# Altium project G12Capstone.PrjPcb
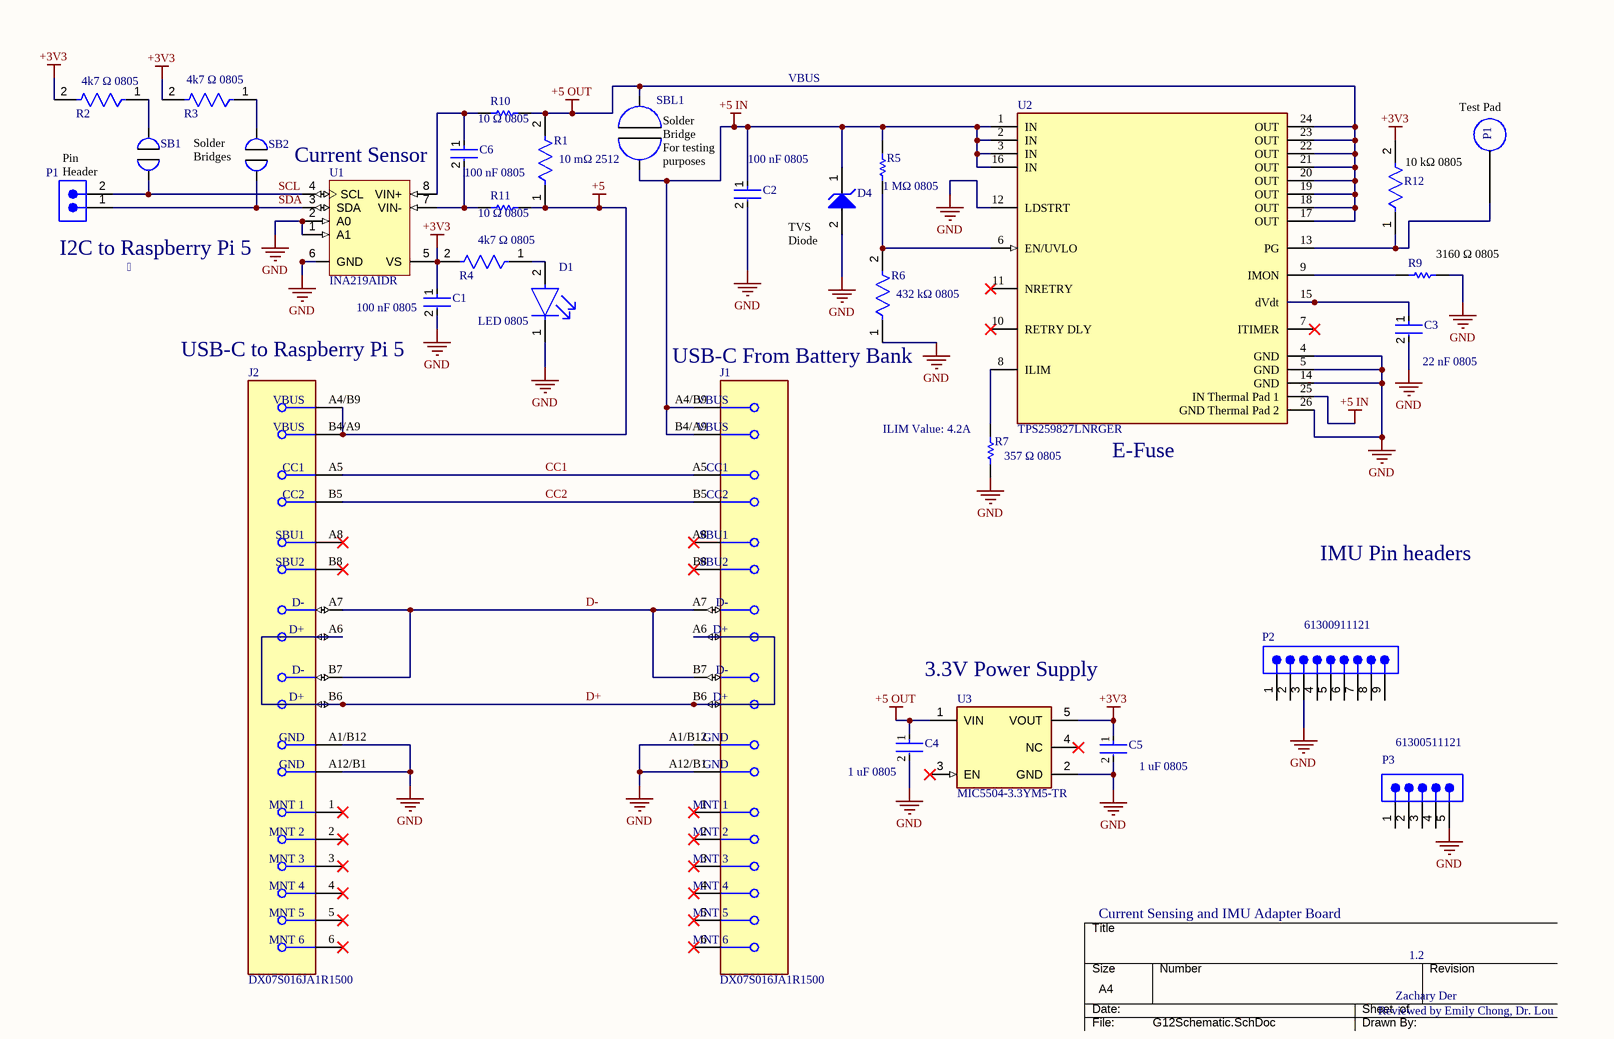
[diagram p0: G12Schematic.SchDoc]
1 sheet, 31 parts. Net scope: global (net labels, ports and power ports of the same name join across sheets).
Board file: G12PCB1.PcbDoc

## Sheet G12Schematic.SchDoc
size A4; SheetNumber: 1; SheetTotal: 1

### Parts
C1  C0805C104K5RACTU  [FP-C0805C-DN-MFG]  (value not drawn)
C2  C0805C104K5RACTU  [FP-C0805C-DN-MFG]  (value not drawn)
C3  C0805C223J1RACAUTO  [FP-C0805C-DN-MFG]  (value not drawn)
C4  08051C105K4T2A  [FP-0805-L_2_01_0_2-W_1_25-MFG]  (value not drawn)
C5  08051C105K4T2A  [FP-0805-L_2_01_0_2-W_1_25-MFG]  (value not drawn)
C6  C0805C104K5RACTU  [FP-C0805C-DN-MFG]  (value not drawn)
D1  APHCM2012CGCK-F01  [FP-APHCM2012CGCK-F01-MFG]  (value not drawn)
D4  SD05T1G  [ONSC-SOD-323-2-477-02_G_V]  (value not drawn)
J1  DX07S016JA1R1500  [FP-DX07S016JA1R1500-MFG]
J2  DX07S016JA1R1500  [FP-DX07S016JA1R1500-MFG]
P1  61300211121  [61300211121]  (value not drawn)
P2  61300911121  [61300911121]
P3  61300511121  [61300511121]
R1  CSRF2512FT10L0  [FP-CSRF2512-IPC_B]  (value not drawn)
R2  CRGCQ0805F4K7  [FP-CRGCQ0805-IPC_C]  (value not drawn)
R3  CRGCQ0805F4K7  [FP-CRGCQ0805-IPC_C]  (value not drawn)
R4  CRGCQ0805F4K7  [FP-CRGCQ0805-IPC_C]  (value not drawn)
R5  RV0805FR-071ML  [RESC2013X60X35NL10T20]  (value not drawn)
R6  CR0805-FX-4323ELF  [FP-CR0805-IPC_A]  (value not drawn)
R7  RC0805FR-07357RL  [RESC2013X60X35ML10T20]  (value not drawn)
R9  RC0805FR-07316RL  [RESC2013X60X35NL10T20]  (value not drawn)
R10  ERJ-6ENF10R0V  [RESC2013X70X40NL20T20]  (value not drawn)
R11  ERJ-6ENF10R0V  [RESC2013X70X40NL20T20]  (value not drawn)
R12  CRGCQ0805J10K  [FP-CRGCQ0805-IPC_C]  (value not drawn)
SB1  Solder Bridge  [Solder Bridge]  (value not drawn)
SB2  Solder Bridge  [Solder Bridge]  (value not drawn)
SBL1  Solder Bridge (Large)  [Solder Bridge (Large)]  (value not drawn)
TP_1  TP_1  [Test Pad]  (value not drawn)  (no BOM)
U1  INA219AIDR  [D0008A_L]
U2  TPS259827LNRGER  [FP-RGE0024M-MFG]
U3  MIC5504-3.3YM5-TR  [FP-SOT23-5LD-PL-1-MFG]

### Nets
+3V3: C1.1 C5.1 R2.2 R3.2 R4.2 R12.2 U1.5(VS) U3.5(VOUT)
+5: J2.A4/B9(VBUS) J2.B4/A9(VBUS) R1.1 R11.2
+5 IN: C2.1 D4.1(K) J1.A4/B9(VBUS) J1.B4/A9(VBUS) R5.2 SBL1.1 U2.1(IN) U2.2(IN) U2.3(IN) U2.16(IN) U2.25(IN_Thermal_Pad_1)
+5 OUT: C4.1 R1.2 R10.2 SBL1.2 U2.17(OUT) U2.18(OUT) U2.19(OUT) U2.20(OUT) U2.21(OUT) U2.22(OUT) U2.23(OUT) U2.24(OUT) U3.1(VIN)
GND: C1.2 C2.2 C3.2 C4.2 C5.2 D1.1(C) D4.2(A) J1.A1/B12(GND) J1.A12/B1(GND) J2.A1/B12(GND) J2.A12/B1(GND) P2.3 P3.5 R6.1 R7.1 R9.2 U1.1(A1) U1.2(A0) U1.6(GND) U2.4(GND) U2.5(GND) U2.12(LDSTRT) U2.14(GND) U2.26(GND_Thermal_Pad_2) U3.2(GND)
CC1: J1.A5(CC1) J2.A5(CC1)
CC2: J1.B5(CC2) J2.B5(CC2)
D+: J1.A6(D+) J1.B6(D+) J2.A6(D+) J2.B6(D+)
D-: J1.A7(D-) J1.B7(D-) J2.A7(D-) J2.B7(D-)
SCL: P1.2 SB1.1 U1.4(SCL)
SDA: P1.1 SB2.1 U1.3(SDA)
NetC3_1: C3.1 U2.15(dVdt)
NetC6_1: C6.1 R10.1 U1.8(VIN+)
NetC6_2: C6.2 R11.1 U1.7(VIN-)
NetD1_2: D1.2(A) R4.1
NetR2_1: R2.1 SB1.2
NetR3_1: R3.1 SB2.2
NetR5_1: R5.1 R6.2 U2.6(EN/UVLO)
NetR7_2: R7.2 U2.8(ILIM)
NetR9_1: R9.1 U2.9(IMON)
NetR12_1: R12.1 TP_1.4 U2.13(PG)

Not connected (* = marked no-connect by the designer): J1 1(MNT_1)* 2(MNT_2)* 3(MNT_3)* 4(MNT_4)* 5(MNT_5)* 6(MNT_6)* A8(SBU1)* B8(SBU2)*; J2 1(MNT_1)* 2(MNT_2)* 3(MNT_3)* 4(MNT_4)* 5(MNT_5)* 6(MNT_6)* A8(SBU1)* B8(SBU2)*; P2 1 2 4 5 6 7 8 9; P3 1 2 3 4; U2 7(ITIMER)* 10(RETRY_DLY)* 11(NRETRY)*; U3 3(EN)* 4(NC)*

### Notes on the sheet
- (near R2) 4k7 Ω 0805
- (near R3) 4k7 Ω 0805
- VBUS
- (near TP_1) Test Pad
- (near P1) Pin Header
- Solder
  Bridges
- Current Sensor
- 100 nF 0805
- (near R10) 10 Ω 0805
- 10 mΩ 2512
- Solder
  Bridge
  For testing purposes
- (near C2) 100 nF 0805
- (near R12) 10 kΩ 0805
- (near R4) 4k7 Ω 0805
- (near R11) 10 Ω 0805
- (near D4) TVS
  Diode
- (near R5) 1 MΩ 0805
- I2C to Raspberry Pi 5
- 
- (near C1) 100 nF 0805
- (near R6) 432 kΩ 0805
- (near R9) 3160 Ω 0805
- USB-C to Raspberry Pi 5
- (near D1) LED 0805
- USB-C From Battery Bank
- (near C3) 22 nF 0805
- (near R7) ILIM Value: 4.2A
- (near R7) 357 Ω 0805
- (near U2) E-Fuse
- IMU Pin headers
- (near U3) 3.3V Power Supply
- (near C4) 1 uF 0805
- (near C5) 1 uF 0805
- Current Sensing and IMU Adapter Board
- 1.2
- Reviewed by Emily Chong, Dr. Lou
- Zachary Der

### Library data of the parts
C1 C2 C6 = CMP-2007-00279-2: CAP CER 0.1UF 50V X7R 0805; Manufacturer: KEMET; Value: 0.10 μF; Tolerance: 0.1; Temperature Coefficient: 30ppm/°C; Material: Ceramic
C3 = CMP-03020-025363-1: C0805 22,000 pF X7R 30ppm/°C 5.00% 100 V; Manufacturer: KEMET; Voltage Rating: 100 V; Material: Ceramic; Tolerance: 0.05
C4 C5 = CMP-07738-122049624-1: 08051C105K4T2A Cap Ceramic 1uF 100V X7R 10% Pad SMD 0805 125C Automotive T/R; Capacitance: 1µF
D1 = CMP-44529-000062-1: LED GREEN CLEAR CHIP SMD; Dominant Wavelength: 570nm; Forward Current: 20mA; Number of LEDs: 1; Luminous Intensity: 40mcd; Forward Voltage: 2.1V; Viewing Angle: 110°
D4 = CMP-1061-00629-1: Transient Voltage Suppressor Diode, for ESD Protection, 2-Pin SOD-323, Pb-Free, Tape and Reel; Manufacturer: On Semiconductor; PPK Max (W): 350; IR Max (uA): 10; Direction: Unidirectional
J1 J2 = CMP-19038-000003-1: CONN RCP USB2.0 TYP C 24P SMD RA
P1 = CMP-1712-00002-7: THT Vertical Pin Header WR-PHD, Pitch 2.54 mm, Single Row, 2 pins; Pitch: 2.54mm; Number of Contacts: 2; Connector Type: Male Pin; Gender: Male; Contact Resistance: 20mΩ; Operating Supply Voltage: 250V; Current Rating: 3A
P2 = CMP-1502-01080-3: NexarPartId: 32855536; Current Rating: 3A; Connector Type: Male Pin; Operating Supply Voltage: 250V; Contact Resistance: 20mΩ; Pitch: 2.54mm; Number of Contacts: 9; Gender: Male
P3 = CMP-1502-01068-4: THT Vertical Pin Header WR-PHD, Pitch 2.54 mm, Single Row, 5 pins; Number of Contacts: 5; Connector Type: Male Pin; Operating Supply Voltage: 250V; Contact Resistance: 20mΩ; Gender: Male; Pitch: 2.54mm; Current Rating: 3A
R1 = CMP-26527-001250-1: Foil on Ceramic Current Sensing Chip Resistor 10mΩ ±1% 2W 2512 AEC Qualified; Resistance: 10mR; Temperature Coefficient: 100ppm/°C
R2-R4 = CMP-03211-010668-1: CRGCQ0805 4.7KΩ 0.125W ±100ppm/°C 1% 150V; Manufacturer: TE Connectivity; Automotive Grade: Grade 837; Tolerance: 0.01
R5 = CMP-2001-01791-1: Manufacturer: Yageo
R6 = CMP-07231-005639-1: Thick Film Chip Resistors 0805 432kΩ 0.125W 1% 100ppm/°C; Voltage Rating: 150V; Resistance: 432kR; Power Rating: 125mW
R7 = CMP-2001-01096-1: Manufacturer: Yageo
R9 = CMP-2001-01081-1: Manufacturer: Yageo
R10 R11 = CMP-1013-00284-2: Manufacturer: Panasonic
R12 = CMP-03211-002989-1: CRGCQ 0805 10K 5%; Manufacturer: TE Connectivity; Voltage Rating: 150V; Temperature Coefficient: ±100ppm/°C; Resistance: 10KΩ; Value: 10KΩ; Power Rating: 0.125W; Tolerance: 0.05; Automotive Grade: Grade 914
TP_1 = Test Pad
U1 = CMP-0704-00003-2: Zero-Drift, Bi-Directional Current / Power Monitor, 3 to 5.5 V, -40 to 125 degC, 8-pin SOIC (D8), Green (RoHS & no Sb/Br); Manufacturer: Texas Instruments; Common Mode Range(Min)(V): 0; SubFamily: Current Shunt Monitor; Rating: Catalog; Input Offset (+/-)(Max)(uV): 100; Vs(Max)(V): 5.5; Common Mode Range(Max)(V): 26; Quiescent Current (+/-)(Typ)(mA): 0.7; Vs(Min)(V): 3; Gain(V/V): 1, 0.5, 0.25, 0.125; Small-Signal Bandwidth(Typ)(MHz): 0.011
U2 = CMP-04913-000057-1: PWR MGMT PWR DISTRIBUTION
U3 = CMP-2000-07604-2: IC REG LINEAR 3.3V 300MA SOT23-5; Quiescent Current: 38uA; Operating Supply Current: 42uA; Max Input Voltage: 5.5V; Min Input Voltage: 2.5V; Output Type: Fixed; Power Supply Rejection Ratio (PSRR): 60dB; Dropout Voltage: 380mV; Accuracy: 3%; Number of Outputs: 1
